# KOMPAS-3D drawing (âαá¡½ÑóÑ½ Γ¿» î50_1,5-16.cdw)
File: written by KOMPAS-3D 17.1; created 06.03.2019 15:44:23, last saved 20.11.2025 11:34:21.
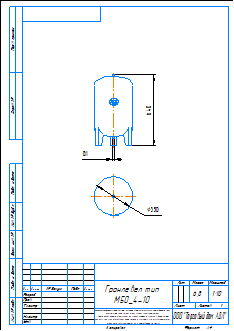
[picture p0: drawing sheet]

Sheet 1: A4, portrait

Title block, sheet 1: name: Гранлевел тип / М50_4-10; mass: 6,8; sheets: 1; sheet format: A4; stored path: C:\Users\kka\KOMPAS_Work\!Trash\ГРАНЛЕВЕЛ тип А Расширительный бак\KOMPAS 2D\Гранлевел тип А100_1,5-16.cdw

Views: Спереди 1, Спереди, Проекционный вид 2
Referenced files in C:\Users\mipv\Desktop\Тип А\SAT\: Гранлевел тип А50_4-10_1.a3d
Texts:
  kka
  adl
  Гранлевел тип А50_4-10
  Рама для чертежей
  Лит-Масса-Масштаб
  Материал-Предприятие
  Масштаб
  Изм.
  Лист
  № докум.
  Подп.
  Дата
  Лит.
  Разраб.
  Пров.
  Т.контр.
  Листов
  Внимание! Данный продукт является объектом авторского права ООО «Торговый Дом АДЛ».
  Запрещается изменение, копирование, распространение
  (в том числе путем копирования на другие сайты и ресурсы в Интернете)
  или любое иное использование информации и объектов без предварительного
  согласия правообладателя (ООО «Торговый Дом АДЛ»).
  Н.контр.
  Утв.
  ООО "Торговый дом АДЛ"
  Изменение
  Номер документа
  Подпись
  Обозначение документа
  Наименование изделия
  Масса изделия по ГОСТ 2.109-73
  Порядковый номер листа
  Общее количество листов в документе
  Характер работы, выполненной лицом, подписавшим документ
  Наименование или индекс предприятия, выпускающего документ
  Инв. № подл.
  Подп. и дата
  Взам. инв. №
  Инв. № дубл.
  Инвентарный номер подлинника по ГОСТ 2.501-68
  Подпись принявшего подлинник в отдел технической документации
  Инвентарный номер подлинника, взамен которого выпущен данный подлинник
  Инвентарный номер дубликата по ГОСТ 2.502-68
  Подпись принявшего дубликат в отдел технической документации
  Справ. №
  Перв. примен.
  Обозначение документа, взамен или на основании которого выпущен данный документ
  Обозначение документа, в котором впервые записан данный документ
  Подпись лица, копировавшего чертеж
  Обозначение формата листа
  !Рама для чертежа
Dimensions and other numbers on the sheet: 640; 350; 1:10; 1; 6,8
